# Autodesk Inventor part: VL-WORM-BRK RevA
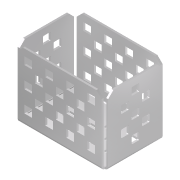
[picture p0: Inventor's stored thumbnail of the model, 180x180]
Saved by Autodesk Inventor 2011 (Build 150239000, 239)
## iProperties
Created: 2007-10
Part Number: VL-WORM-BRK RevA
Material: Steel
Document SubType Name: Modeling
Density: 7.85 g/cm^3
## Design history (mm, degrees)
feature "Base1"
workplane "Work Plane1"
sketch "Sketch1"
  geometry: L1 (29.794, 38.811)-(3.175, 38.811) reference; L2 (3.175, 38.811)-(0, 35.636) reference; L3 (0, 35.636)-(0, 0) reference; L4 (32.969, 0)-(0, 0) reference; L5 (32.969, 0)-(32.969, 35.636) reference; L6 (32.969, 35.636)-(29.794, 38.811) reference; L7 (18.796, 5.258)-(18.796, 8.865) reference; L8 (14.681, 4.75)-(18.288, 4.75) reference; L9 (14.173, 8.865)-(14.173, 5.258) reference; L10 (18.288, 9.373)-(14.681, 9.373) reference; L11 (12.446, 11.608)-(12.446, 15.215) reference; L12 (8.331, 11.1)-(11.938, 11.1) reference; L13 (7.823, 15.215)-(7.823, 11.608) reference; L14 (11.938, 15.723)-(8.331, 15.723) reference; L15 (18.796, 17.958)-(18.796, 21.565) reference; L16 (14.681, 17.45)-(18.288, 17.45) reference; L17 (14.173, 21.565)-(14.173, 17.958) reference; L18 (18.288, 22.073)-(14.681, 22.073) reference; L19 (12.446, 24.308)-(12.446, 27.915) reference; L20 (8.331, 23.8)-(11.938, 23.8) reference; L21 (7.823, 27.915)-(7.823, 24.308) reference; L22 (11.938, 28.423)-(8.331, 28.423) reference; L23 (18.796, 30.658)-(18.796, 34.265) reference; L24 (14.681, 30.15)-(18.288, 30.15) reference; L25 (14.173, 34.265)-(14.173, 30.658) reference; L26 (18.288, 34.773)-(14.681, 34.773) reference; L27 (20.523, 24.308)-(20.523, 27.915) reference; L28 (21.031, 28.423)-(24.638, 28.423) reference; L29 (25.146, 27.915)-(25.146, 24.308) reference; L30 (24.638, 23.8)-(21.031, 23.8) reference; L31 (20.523, 11.608)-(20.523, 15.215) reference; L32 (21.031, 15.723)-(24.638, 15.723) reference; L33 (25.146, 15.215)-(25.146, 11.608) reference; L34 (24.638, 11.1)-(21.031, 11.1) reference; C1 r 2.311 at (16.485, 32.461); C2 r 2.311 at (16.485, 7.061); A1 r 0.508 centre (18.288, 8.865) between (18.796, 8.865) and (18.288, 9.373) reference; A2 r 0.508 centre (18.288, 5.258) between (18.288, 4.75) and (18.796, 5.258) reference; A3 r 0.508 centre (14.681, 5.258) between (14.173, 5.258) and (14.681, 4.75) reference; A4 r 0.508 centre (14.681, 8.865) between (14.681, 9.373) and (14.173, 8.865) reference; A5 r 0.508 centre (11.938, 15.215) between (12.446, 15.215) and (11.938, 15.723) reference; A6 r 0.508 centre (11.938, 11.608) between (11.938, 11.1) and (12.446, 11.608) reference; A7 r 0.508 centre (8.331, 11.608) between (7.823, 11.608) and (8.331, 11.1) reference; A8 r 0.508 centre (8.331, 15.215) between (8.331, 15.723) and (7.823, 15.215) reference; A9 r 0.508 centre (18.288, 21.565) between (18.796, 21.565) and (18.288, 22.073) reference; A10 r 0.508 centre (18.288, 17.958) between (18.288, 17.45) and (18.796, 17.958) reference; A11 r 0.508 centre (14.681, 17.958) between (14.173, 17.958) and (14.681, 17.45) reference; A12 r 0.508 centre (14.681, 21.565) between (14.681, 22.073) and (14.173, 21.565) reference; A13 r 0.508 centre (11.938, 27.915) between (12.446, 27.915) and (11.938, 28.423) reference; A14 r 0.508 centre (11.938, 24.308) between (11.938, 23.8) and (12.446, 24.308) reference; A15 r 0.508 centre (8.331, 24.308) between (7.823, 24.308) and (8.331, 23.8) reference; A16 r 0.508 centre (8.331, 27.915) between (8.331, 28.423) and (7.823, 27.915) reference; A17 r 0.508 centre (18.288, 34.265) between (18.796, 34.265) and (18.288, 34.773) reference; A18 r 0.508 centre (18.288, 30.658) between (18.288, 30.15) and (18.796, 30.658) reference; A19 r 0.508 centre (14.681, 30.658) between (14.173, 30.658) and (14.681, 30.15) reference; A20 r 0.508 centre (14.681, 34.265) between (14.681, 34.773) and (14.173, 34.265) reference; A21 r 0.508 centre (21.031, 27.915) between (21.031, 28.423) and (20.523, 27.915) reference; A22 r 0.508 centre (24.638, 27.915) between (25.146, 27.915) and (24.638, 28.423) reference; A23 r 0.508 centre (24.638, 24.308) between (24.638, 23.8) and (25.146, 24.308) reference; A24 r 0.508 centre (21.031, 24.308) between (20.523, 24.308) and (21.031, 23.8) reference; A25 r 0.508 centre (21.031, 15.215) between (21.031, 15.723) and (20.523, 15.215) reference; A26 r 0.508 centre (24.638, 15.215) between (25.146, 15.215) and (24.638, 15.723) reference; A27 r 0.508 centre (24.638, 11.608) between (24.638, 11.1) and (25.146, 11.608) reference; A28 r 0.508 centre (21.031, 11.608) between (20.523, 11.608) and (21.031, 11.1) reference
  constraints: 8 tangent, 2 centre point
sketch "Sketch2"
  geometry: L1 (0, 35.636)-(0, 0) reference; L2 (0, 35.636)-(-3.175, 38.811) reference; L3 (-29.794, 38.811)-(-3.175, 38.811) reference; L4 (-29.794, 38.811)-(-32.969, 35.636) reference; L5 (-32.969, 0)-(-32.969, 35.636) reference; L6 (0, 0)-(-32.969, 0) reference; L7 (-14.681, 9.373)-(-18.288, 9.373) reference; L8 (-14.173, 5.258)-(-14.173, 8.865) reference; L9 (-18.288, 4.75)-(-14.681, 4.75) reference; L10 (-18.796, 8.865)-(-18.796, 5.258) reference; L11 (-8.331, 15.723)-(-11.938, 15.723) reference; L12 (-7.823, 11.608)-(-7.823, 15.215) reference; L13 (-11.938, 11.1)-(-8.331, 11.1) reference; L14 (-12.446, 15.215)-(-12.446, 11.608) reference; L15 (-14.681, 22.073)-(-18.288, 22.073) reference; L16 (-14.173, 17.958)-(-14.173, 21.565) reference; L17 (-18.288, 17.45)-(-14.681, 17.45) reference; L18 (-18.796, 21.565)-(-18.796, 17.958) reference; L19 (-8.331, 28.423)-(-11.938, 28.423) reference; L20 (-7.823, 24.308)-(-7.823, 27.915) reference; L21 (-11.938, 23.8)-(-8.331, 23.8) reference; L22 (-12.446, 27.915)-(-12.446, 24.308) reference; L23 (-14.681, 34.773)-(-18.288, 34.773) reference; L24 (-14.173, 30.658)-(-14.173, 34.265) reference; L25 (-18.288, 30.15)-(-14.681, 30.15) reference; L26 (-18.796, 34.265)-(-18.796, 30.658) reference; L27 (-24.638, 28.423)-(-21.031, 28.423) reference; L28 (-20.523, 27.915)-(-20.523, 24.308) reference; L29 (-21.031, 23.8)-(-24.638, 23.8) reference; L30 (-25.146, 24.308)-(-25.146, 27.915) reference; L31 (-24.638, 15.723)-(-21.031, 15.723) reference; L32 (-20.523, 15.215)-(-20.523, 11.608) reference; L33 (-21.031, 11.1)-(-24.638, 11.1) reference; L34 (-25.146, 11.608)-(-25.146, 15.215) reference; C1 r 2.311 at (-16.485, 32.461); C2 r 2.311 at (-16.485, 7.061); A1 r 0.508 centre (-18.288, 8.865) between (-18.288, 9.373) and (-18.796, 8.865) reference; A2 r 0.508 centre (-14.681, 8.865) between (-14.173, 8.865) and (-14.681, 9.373) reference; A3 r 0.508 centre (-14.681, 5.258) between (-14.681, 4.75) and (-14.173, 5.258) reference; A4 r 0.508 centre (-18.288, 5.258) between (-18.796, 5.258) and (-18.288, 4.75) reference; A5 r 0.508 centre (-11.938, 15.215) between (-11.938, 15.723) and (-12.446, 15.215) reference; A6 r 0.508 centre (-8.331, 15.215) between (-7.823, 15.215) and (-8.331, 15.723) reference; A7 r 0.508 centre (-8.331, 11.608) between (-8.331, 11.1) and (-7.823, 11.608) reference; A8 r 0.508 centre (-11.938, 11.608) between (-12.446, 11.608) and (-11.938, 11.1) reference; A9 r 0.508 centre (-18.288, 21.565) between (-18.288, 22.073) and (-18.796, 21.565) reference; A10 r 0.508 centre (-14.681, 21.565) between (-14.173, 21.565) and (-14.681, 22.073) reference; A11 r 0.508 centre (-14.681, 17.958) between (-14.681, 17.45) and (-14.173, 17.958) reference; A12 r 0.508 centre (-18.288, 17.958) between (-18.796, 17.958) and (-18.288, 17.45) reference; A13 r 0.508 centre (-11.938, 27.915) between (-11.938, 28.423) and (-12.446, 27.915) reference; A14 r 0.508 centre (-8.331, 27.915) between (-7.823, 27.915) and (-8.331, 28.423) reference; A15 r 0.508 centre (-8.331, 24.308) between (-8.331, 23.8) and (-7.823, 24.308) reference; A16 r 0.508 centre (-11.938, 24.308) between (-12.446, 24.308) and (-11.938, 23.8) reference; A17 r 0.508 centre (-18.288, 34.265) between (-18.288, 34.773) and (-18.796, 34.265) reference; A18 r 0.508 centre (-14.681, 34.265) between (-14.173, 34.265) and (-14.681, 34.773) reference; A19 r 0.508 centre (-14.681, 30.658) between (-14.681, 30.15) and (-14.173, 30.658) reference; A20 r 0.508 centre (-18.288, 30.658) between (-18.796, 30.658) and (-18.288, 30.15) reference; A21 r 0.508 centre (-21.031, 27.915) between (-20.523, 27.915) and (-21.031, 28.423) reference; A22 r 0.508 centre (-21.031, 24.308) between (-21.031, 23.8) and (-20.523, 24.308) reference; A23 r 0.508 centre (-24.638, 24.308) between (-25.146, 24.308) and (-24.638, 23.8) reference; A24 r 0.508 centre (-24.638, 27.915) between (-24.638, 28.423) and (-25.146, 27.915) reference; A25 r 0.508 centre (-21.031, 15.215) between (-20.523, 15.215) and (-21.031, 15.723) reference; A26 r 0.508 centre (-21.031, 11.608) between (-21.031, 11.1) and (-20.523, 11.608) reference; A27 r 0.508 centre (-24.638, 11.608) between (-25.146, 11.608) and (-24.638, 11.1) reference; A28 r 0.508 centre (-24.638, 15.215) between (-24.638, 15.723) and (-25.146, 15.215) reference
  constraints: 6 tangent, 2 centre point
sketch "Sketch3"
  geometry: L1 (3.175, 38.811)-(47.625, 38.811) reference; L2 (3.175, 38.811)-(0, 35.636) reference; L3 (0, 0)-(0, 35.636) reference; L4 (50.8, 0)-(0, 0) reference; L5 (50.8, 35.636)-(50.8, 0) reference; L6 (50.8, 35.636)-(47.625, 38.811) reference; L7 (46.761, 30.15)-(46.761, 34.773) reference; L8 (42.139, 30.15)-(46.761, 30.15) reference; L9 (42.139, 34.773)-(42.139, 30.15) reference; L10 (46.761, 34.773)-(42.139, 34.773) reference; L11 (34.061, 30.15)-(34.061, 34.773) reference; L12 (29.439, 30.15)-(34.061, 30.15) reference; L13 (29.439, 34.773)-(29.439, 30.15) reference; L14 (34.061, 34.773)-(29.439, 34.773) reference; L15 (21.361, 30.15)-(21.361, 34.773) reference; L16 (16.739, 30.15)-(21.361, 30.15) reference; L17 (16.739, 34.773)-(16.739, 30.15) reference; L18 (21.361, 34.773)-(16.739, 34.773) reference; L19 (8.661, 30.15)-(8.661, 34.773) reference; L20 (4.039, 30.15)-(8.661, 30.15) reference; L21 (4.039, 34.773)-(4.039, 30.15) reference; L22 (8.661, 34.773)-(4.039, 34.773) reference; L23 (40.411, 23.8)-(40.411, 28.423) reference; L24 (35.789, 23.8)-(40.411, 23.8) reference; L25 (35.789, 28.423)-(35.789, 23.8) reference; L26 (40.411, 28.423)-(35.789, 28.423) reference; L27 (27.711, 23.8)-(27.711, 28.423) reference; L28 (23.089, 23.8)-(27.711, 23.8) reference; L29 (23.089, 28.423)-(23.089, 23.8) reference; L30 (27.711, 28.423)-(23.089, 28.423) reference; L31 (15.011, 23.8)-(15.011, 28.423) reference; L32 (10.389, 23.8)-(15.011, 23.8) reference; L33 (10.389, 28.423)-(10.389, 23.8) reference; L34 (15.011, 28.423)-(10.389, 28.423) reference; L35 (46.761, 17.45)-(46.761, 22.073) reference; L36 (42.139, 17.45)-(46.761, 17.45) reference; L37 (42.139, 22.073)-(42.139, 17.45) reference; L38 (46.761, 22.073)-(42.139, 22.073) reference; L39 (34.061, 17.45)-(34.061, 22.073) reference; L40 (29.439, 17.45)-(34.061, 17.45) reference; L41 (29.439, 22.073)-(29.439, 17.45) reference; L42 (34.061, 22.073)-(29.439, 22.073) reference; L43 (21.361, 17.45)-(21.361, 22.073) reference; L44 (16.739, 17.45)-(21.361, 17.45) reference; L45 (16.739, 22.073)-(16.739, 17.45) reference; L46 (21.361, 22.073)-(16.739, 22.073) reference; L47 (8.661, 17.45)-(8.661, 22.073) reference; L48 (4.039, 17.45)-(8.661, 17.45) reference; L49 (4.039, 22.073)-(4.039, 17.45) reference; L50 (8.661, 22.073)-(4.039, 22.073) reference; L51 (40.411, 11.1)-(40.411, 15.723) reference; L52 (35.789, 11.1)-(40.411, 11.1) reference; L53 (35.789, 15.723)-(35.789, 11.1) reference; L54 (40.411, 15.723)-(35.789, 15.723) reference; L55 (27.711, 11.1)-(27.711, 15.723) reference; L56 (23.089, 11.1)-(27.711, 11.1) reference; L57 (23.089, 15.723)-(23.089, 11.1) reference; L58 (27.711, 15.723)-(23.089, 15.723) reference; L59 (15.011, 11.1)-(15.011, 15.723) reference; L60 (10.389, 11.1)-(15.011, 11.1) reference; L61 (10.389, 15.723)-(10.389, 11.1) reference; L62 (15.011, 15.723)-(10.389, 15.723) reference; L63 (46.761, 4.75)-(46.761, 9.373) reference; L64 (42.139, 4.75)-(46.761, 4.75) reference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; C1 r 2.311 at (12.7, 26.111); C2 r 2.311 at (38.1, 26.111)
  constraints: 7 tangent, 2 centre point
sketch "Sketch4"
  geometry: L1 (50.8, 0)-(50.8, 35.636) reference; L2 (50.8, 35.636)-(47.625, 38.811) reference; L3 (47.625, 38.811)-(3.175, 38.811) reference; L4 (3.175, 38.811)-(0, 35.636) reference; L5 (0, 35.636)-(0, 0) reference; L6 (50.8, 0)-(0, 0) reference; L7 (4.039, 34.773)-(4.039, 30.15) reference; L8 (8.661, 34.773)-(4.039, 34.773) reference; L9 (8.661, 30.15)-(8.661, 34.773) reference; L10 (4.039, 30.15)-(8.661, 30.15) reference; L11 (16.739, 30.15)-(21.361, 30.15) reference; L12 (16.739, 34.773)-(16.739, 30.15) reference; L13 (21.361, 34.773)-(16.739, 34.773) reference; L14 (21.361, 30.15)-(21.361, 34.773) reference; L15 (29.439, 30.15)-(34.061, 30.15) reference; L16 (29.439, 34.773)-(29.439, 30.15) reference; L17 (34.061, 34.773)-(29.439, 34.773) reference; L18 (34.061, 30.15)-(34.061, 34.773) reference; L19 (42.139, 30.15)-(46.761, 30.15) reference; L20 (42.139, 34.773)-(42.139, 30.15) reference; L21 (46.761, 34.773)-(42.139, 34.773) reference; L22 (46.761, 30.15)-(46.761, 34.773) reference; L23 (10.389, 23.8)-(15.011, 23.8) reference; L24 (10.389, 28.423)-(10.389, 23.8) reference; L25 (15.011, 28.423)-(10.389, 28.423) reference; L26 (15.011, 23.8)-(15.011, 28.423) reference; L27 (23.089, 23.8)-(27.711, 23.8) reference; L28 (23.089, 28.423)-(23.089, 23.8) reference; L29 (27.711, 28.423)-(23.089, 28.423) reference; L30 (27.711, 23.8)-(27.711, 28.423) reference; L31 (35.789, 23.8)-(40.411, 23.8) reference; L32 (35.789, 28.423)-(35.789, 23.8) reference; L33 (40.411, 28.423)-(35.789, 28.423) reference; L34 (40.411, 23.8)-(40.411, 28.423) reference; L35 (4.039, 17.45)-(8.661, 17.45) reference; L36 (4.039, 22.073)-(4.039, 17.45) reference; L37 (8.661, 22.073)-(4.039, 22.073) reference; L38 (8.661, 17.45)-(8.661, 22.073) reference; L39 (16.739, 17.45)-(21.361, 17.45) reference; L40 (16.739, 22.073)-(16.739, 17.45) reference; L41 (21.361, 22.073)-(16.739, 22.073) reference; L42 (21.361, 17.45)-(21.361, 22.073) reference; L43 (29.439, 17.45)-(34.061, 17.45) reference; L44 (29.439, 22.073)-(29.439, 17.45) reference; L45 (34.061, 22.073)-(29.439, 22.073) reference; L46 (34.061, 17.45)-(34.061, 22.073) reference; L47 (42.139, 17.45)-(46.761, 17.45) reference; L48 (42.139, 22.073)-(42.139, 17.45) reference; L49 (46.761, 22.073)-(42.139, 22.073) reference; L50 (46.761, 17.45)-(46.761, 22.073) reference; L51 (10.389, 11.1)-(15.011, 11.1) reference; L52 (10.389, 15.723)-(10.389, 11.1) reference; L53 (15.011, 15.723)-(10.389, 15.723) reference; L54 (15.011, 11.1)-(15.011, 15.723) reference; L55 (23.089, 11.1)-(27.711, 11.1) reference; L56 (23.089, 15.723)-(23.089, 11.1) reference; L57 (27.711, 15.723)-(23.089, 15.723) reference; L58 (27.711, 11.1)-(27.711, 15.723) reference; L59 (35.789, 11.1)-(40.411, 11.1) reference; L60 (35.789, 15.723)-(35.789, 11.1) reference; L61 (40.411, 15.723)-(35.789, 15.723) reference; L62 (40.411, 11.1)-(40.411, 15.723) reference; L63 (4.039, 4.75)-(8.661, 4.75) reference; L64 (4.039, 9.373)-(4.039, 4.75) reference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; C1 r 2.311 at (12.7, 26.111); C2 r 2.311 at (38.1, 26.111)
  constraints: 8 tangent, 2 centre point
workplane "Work Plane2"
sketch "Sketch5"
  geometry: L1 (23.089, 23.8)-(27.711, 23.8) reference; L2 (23.089, 28.423)-(23.089, 23.8) reference; L3 (27.711, 28.423)-(23.089, 28.423) reference; L4 (27.711, 23.8)-(27.711, 28.423) reference; C1 r 2.311 at (25.4, 26.111)
  constraints: 4 tangent, 1 centre point
extrude "Extrusion1" join sketch "Sketch5" distance "d0" = 31.75; taper "d1" = 0 deg
sketch "Sketch6"
  geometry: L1 (-14.681, 9.373)-(-18.288, 9.373) reference; L2 (-14.173, 5.258)-(-14.173, 8.865) reference; L3 (-18.288, 4.75)-(-14.681, 4.75) reference; L4 (-18.796, 8.865)-(-18.796, 5.258) reference; C1 r 2.311 at (-16.485, 7.061)
  constraints: 4 tangent, 1 centre point
extrude "Extrusion2" join sketch "Sketch6" distance "d2" = 38.1; taper "d3" = 0 deg
body "Solid1"
split "Split1"
